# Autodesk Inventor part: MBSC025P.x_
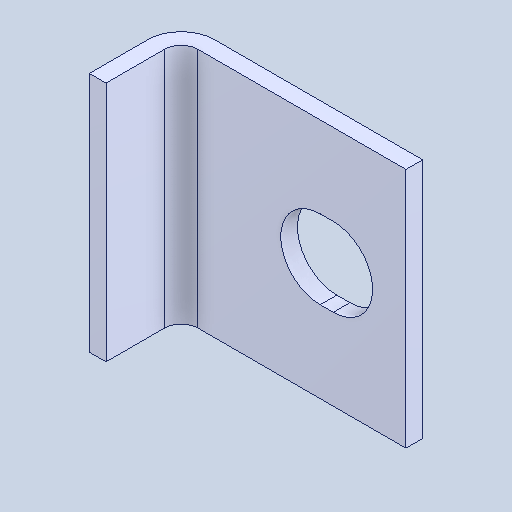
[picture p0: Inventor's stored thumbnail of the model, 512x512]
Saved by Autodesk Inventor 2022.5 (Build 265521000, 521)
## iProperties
Created: 2024-05
Part Number: MBSC025P.x_
Material: 一般
Document SubType Name: Modeling
Designer: ImaoCorp
Density: 1 g/cm^3
Appearance: 既定
Author: ImaoCorp
Sending System: SOLIDWORKS 2022-2022290
MC: AMD64
MC_MODEL: Intel64 Family 6 Model 60 Stepping 3, GenuineIntel
OS: Windows_NT
FRU: Parasolid Version 33.1, build 260,  4-25-2022
FORMAT: text
GUISE: transmit
KEY: FILEMBSC025P.x_t
DATE: Mon May 20 16:27:41 2024
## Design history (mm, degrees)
feature "Base1"
node "ソリッド1"
